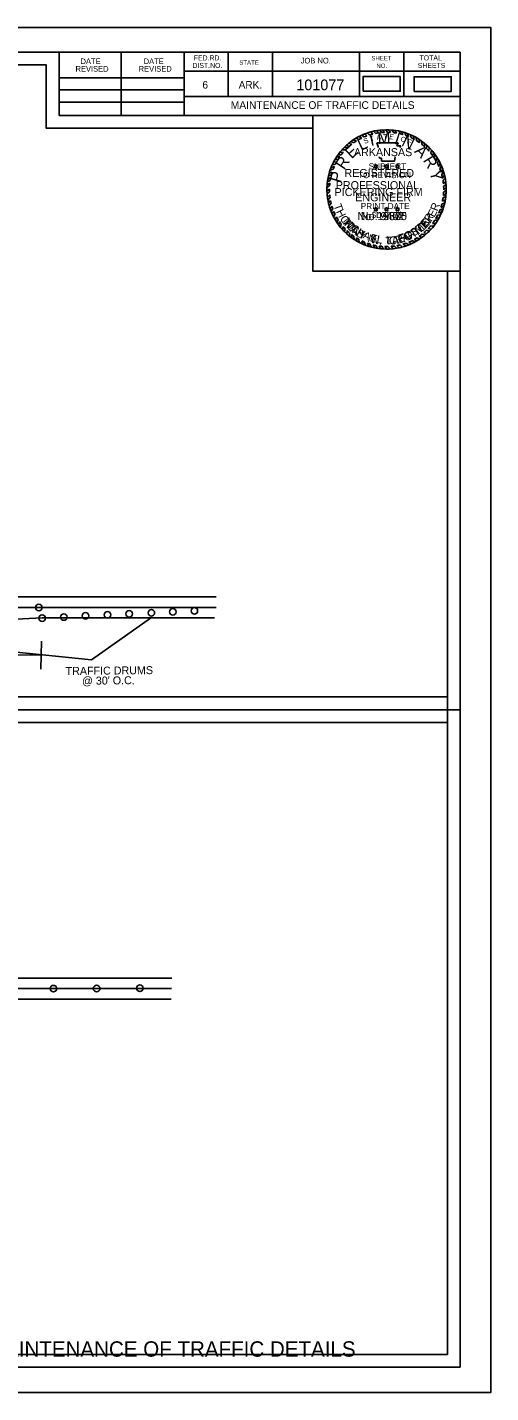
# Model space of a CAD drawing. Extents: x 13528 to 25043, y 7635 to 10612.
# Drawn here: x 18896 to 19258, y 9545 to 10612 of the extents above; entities that cross this region are included whole.
import ezdxf

# ---------------------------------------------------------------- set-up
doc = ezdxf.new("R2010")
doc.units = 0
for name, color, linetype in [('Default', 7, 'Continuous'), ('R_Border', 7, 'Continuous'), ('R_Border Notes', 7, 'Continuous'), ('R_Border Plan-Plan', 7, 'Continuous'), ('R_Draft', 7, 'Continuous'), ('R_Revision Date Text', 7, 'Continuous'), ('STAMP_PE_CRAFTON', 7, 'Continuous'), ('STAMP_PE_FOSTER', 7, 'Continuous'), ('STAMP_PE_SEAL-INFO', 7, 'Continuous'), ('STAMP_PE_TAEGTMEYER', 7, 'Continuous'), ('STAMP_PE_TXT', 7, 'Continuous')]:
    doc.layers.add(name, color=color, linetype=linetype)

# ---------------------------------------------------------------- blocks, each defined once
blk = doc.blocks.new('DOT')
at = {"layer": 'Default'}
blk.add_circle((-0.4, -0.3), 3.75, dxfattribs=at)

msp = doc.modelspace()

# ---------------------------------------------------------------- linework, layer by layer
at = {"layer": 'Default'}
for p, q in [((18002.2, 10166.6), (19044, 10166.6)), ((18002, 10158.4), (19043.8, 10158.4)), ((18737.5, 10142.1), (18908.1, 10150.2)), ((18908.2, 10150.2), (19042.6, 10150.2)), ((18907.6, 10131.9), (18907.1, 10110.1)), ((17907.8, 9868.7), (19009.2, 9868.7)), ((17907.6, 9860.5), (19009, 9860.5)), ((18865.7, 9852.3), (19008.8, 9852.3))]:
    msp.add_line(p, q, dxfattribs=at)
for points in [[(19158.6, 10561.6), (19187.7, 10561.6), (19187.7, 10573.1), (19158.6, 10573.1)], [(19198.5, 10561.4), (19227.5, 10561.4), (19227.5, 10572.9), (19198.5, 10572.9)]]:
    msp.add_lwpolyline(points, close=True, dxfattribs=at)
at = {"layer": 'R_Border'}
for p, q in [((18992.7, 10149.9), (18946.7, 10117.4)), ((18747, 10137.5), (18946.7, 10117.4)), ((18737.1, 10122.2), (18907.3, 10121))]:
    msp.add_line(p, q, dxfattribs=at)
at = {"layer": 'R_Border Plan-Plan'}
msp.add_line((17653.6, 10078.4), (19234.5, 10078.4), dxfattribs=at)
at = {"layer": 'R_Draft'}
for p, q in [((17653.6, 10592.1), (19234.5, 10592.1)), ((18921.3, 10542.7), (18921.3, 10592.1)), ((18969.7, 10542.7), (18969.7, 10592.1)), ((19019, 10592.1), (19019, 10542.7)), ((19053.2, 10592.1), (19053.2, 10557.4)), ((19087.9, 10592.1), (19087.9, 10557.4)), ((19155.8, 10592.1), (19155.8, 10557.4)), ((19190.5, 10592.1), (19190.5, 10557.4)), ((19234.5, 9564.8), (19234.5, 10592.1)), ((18921.3, 10572), (19019, 10572)), ((19234.5, 10577.4), (19019, 10577.4)), ((19234.5, 10577.5), (19234.5, 10577.5)), ((18921.3, 10562.7), (19019, 10562.7)), ((18921.3, 10553), (19019, 10553)), ((19234.5, 10557.4), (19019, 10557.4)), ((19033.8, 10557.4), (19234.5, 10557.4)), ((19234.5, 10542.7), (18921.3, 10542.7)), ((19234.5, 9564.8), (17653.6, 9564.8))]:
    msp.add_line(p, q, dxfattribs=at)
at = {"layer": 'R_Revision Date Text'}
for points in [[(17591.6, 10611.5), (19258.3, 10611.5), (19258.3, 9544.9), (17591.6, 9544.9)], [(19224.5, 10088.4), (17663.6, 10088.4), (17663.6, 10582.1), (18911.3, 10582.1), (18911.3, 10532.7), (18999, 10532.7), (19119.5, 10532.7), (19119.5, 10421), (19224.5, 10421)], [(17663.6, 10582.1), (18911.3, 10582.1), (18911.3, 10532.7), (18999, 10532.7), (19119.5, 10532.7), (19119.5, 10421), (19224.5, 10421), (19224.5, 9574.8), (17663.6, 9574.8)], [(19119.5, 10542.7), (19234.5, 10542.7), (19234.5, 10421), (19119.5, 10421)], [(17663.6, 10068.4), (19224.5, 10068.4), (19224.5, 9574.8), (17663.6, 9574.8)]]:
    msp.add_lwpolyline(points, close=True, dxfattribs=at)
at = {"layer": 'STAMP_PE_SEAL-INFO'}
for p, q in [((19160, 10528.3), (19161.5, 10526.7)), ((19161.8, 10529), (19163.7, 10527.4)), ((19164.7, 10529.9), (19166.2, 10528.1)), ((19166.7, 10530.3), (19168.5, 10528.6)), ((19169.1, 10530.8), (19170.6, 10529)), ((19171.7, 10531.2), (19173.1, 10529.3)), ((19175.3, 10529.4), (19173.8, 10531.4)), ((19177.8, 10529.4), (19176.4, 10531.5)), ((19180.1, 10529.3), (19178.8, 10531.5)), ((19182.7, 10529.1), (19181.2, 10531.3)), ((19184.8, 10528.8), (19183.5, 10531)), ((19187.6, 10528.2), (19186.7, 10530.5)), ((19189.6, 10527.6), (19188.8, 10530)), ((19191.9, 10526.9), (19191.2, 10529.3)), ((19194, 10526.1), (19193.2, 10528.6)), ((19143.8, 10517.6), (19146.5, 10517.4)), ((19145.5, 10519.2), (19147.8, 10518.5)), ((19147.2, 10520.7), (19149.8, 10520.2)), ((19149.1, 10522.4), (19151.4, 10521.3)), ((19151.2, 10523.7), (19153.4, 10522.7)), ((19153.1, 10524.9), (19155.3, 10523.8)), ((19155.4, 10526.2), (19157.7, 10525)), ((19157.5, 10527.2), (19159.5, 10525.9)), ((19169.4, 10521.3), (19186.1, 10521.3)), ((19170, 10519.8), (19169.4, 10521.3)), ((19170.5, 10518.3), (19170, 10519.8)), ((19170.5, 10517.7), (19170.5, 10518.3)), ((19186.1, 10521.3), (19184.9, 10518.9)), ((19184.9, 10518.9), (19188.1, 10518.9)), ((19188.1, 10518.9), (19187.4, 10517.7)), ((19196.3, 10525.1), (19195.7, 10527.6)), ((19198.5, 10523.9), (19198.1, 10526.5)), ((19200.4, 10522.8), (19200.2, 10525.3)), ((19202.6, 10521.4), (19202.4, 10523.9)), ((19204.4, 10520), (19204.6, 10522.5)), ((19206.6, 10518.2), (19206.7, 10520.8)), ((19208.2, 10516.7), (19208.5, 10519.2)), ((19136.7, 10508.3), (19139.1, 10508.4)), ((19137.9, 10510.3), (19140.5, 10510.4)), ((19139.1, 10512), (19141.6, 10512)), ((19140.5, 10513.8), (19143.2, 10513.9)), ((19142.2, 10515.9), (19144.8, 10515.7)), ((19171.5, 10509.2), (19171.3, 10510.3)), ((19173, 10509.2), (19171.5, 10509.2)), ((19173, 10507), (19173, 10509.2)), ((19183.2, 10507), (19173, 10507)), ((19183.3, 10508.7), (19183.2, 10507)), ((19183.7, 10510.3), (19183.3, 10508.7)), ((19210, 10514.8), (19210.3, 10517.5)), ((19211.4, 10513.3), (19212, 10515.6)), ((19213, 10511.2), (19213.7, 10513.7)), ((19214.1, 10509.6), (19215, 10511.9)), ((19215.6, 10507.1), (19216.5, 10509.6)), ((19216.6, 10505.3), (19217.8, 10507.5)), ((19131.6, 10495.5), (19133.9, 10496.4)), ((19132.1, 10497.5), (19134.5, 10498.3)), ((19132.9, 10500), (19135.3, 10500.7)), ((19133.6, 10502), (19136.2, 10502.8)), ((19134.6, 10504.2), (19137.1, 10504.7)), ((19135.5, 10506.1), (19138, 10506.5)), ((19217.8, 10502.9), (19218.9, 10505.3)), ((19218.5, 10501.2), (19219.8, 10503.3)), ((19219.5, 10498.4), (19220.8, 10500.8)), ((19220, 10496.6), (19221.5, 10498.9)), ((19132.5, 10487.6), (19130.4, 10486.3)), ((19132.7, 10489.8), (19130.5, 10488.3)), ((19133, 10491.9), (19130.8, 10490.8)), ((19133.4, 10494.2), (19131.1, 10493)), ((19220.7, 10493.8), (19222.2, 10496)), ((19221, 10491.9), (19222.8, 10493.7)), ((19221.3, 10489.4), (19223.2, 10491)), ((19221.5, 10487.3), (19223.4, 10488.7)), ((19221.6, 10484.7), (19223.6, 10486.3)), ((19132.4, 10485.2), (19130.4, 10483.5)), ((19132.5, 10483.1), (19130.5, 10481.5)), ((19132.6, 10480.6), (19130.8, 10478.9)), ((19132.9, 10478.5), (19131.1, 10476.6)), ((19133.3, 10476.2), (19131.6, 10474.4)), ((19220.6, 10475.7), (19222.9, 10476.7)), ((19221, 10478.2), (19223.3, 10479.3)), ((19221.3, 10480.1), (19223.5, 10481.4)), ((19221.5, 10482.7), (19223.6, 10484)), ((19133.7, 10474.1), (19132.2, 10472)), ((19134.4, 10471.9), (19132.9, 10469.8)), ((19135.1, 10469.8), (19133.7, 10467.7)), ((19135.9, 10467.6), (19134.6, 10465.5)), ((19136.8, 10465.7), (19135.6, 10463.4)), ((19216.8, 10464.8), (19219.2, 10465.1)), ((19217.6, 10466.5), (19220, 10467)), ((19218.6, 10469), (19221.1, 10469.7)), ((19219.3, 10470.9), (19221.8, 10472)), ((19220.1, 10473.4), (19222.4, 10474.4)), ((19137.9, 10463.4), (19137, 10461)), ((19139.1, 10461.4), (19138.2, 10459.1)), ((19140.1, 10459.8), (19139.6, 10457.1)), ((19141.5, 10457.9), (19141, 10455.2)), ((19143, 10456), (19142.6, 10453.4)), ((19144.6, 10454.3), (19144.2, 10451.7)), ((19209.4, 10454.3), (19211.8, 10453.9)), ((19211.3, 10456.5), (19213.6, 10456.1)), ((19212.9, 10458.4), (19215.4, 10458.4)), ((19214.6, 10460.9), (19216.9, 10460.9)), ((19215.4, 10462.3), (19217.9, 10462.6)), ((19146.2, 10452.7), (19146, 10450)), ((19147.9, 10451.1), (19147.9, 10448.5)), ((19149.7, 10449.7), (19149.8, 10447)), ((19151.4, 10448.4), (19151.6, 10445.8)), ((19153.5, 10447), (19153.8, 10444.4)), ((19155.3, 10446), (19155.7, 10443.4)), ((19157.7, 10444.7), (19158.5, 10442.1)), ((19159.5, 10443.9), (19160.4, 10441.3)), ((19162, 10442.9), (19163, 10440.4)), ((19192.2, 10443), (19194.4, 10441.7)), ((19194.3, 10443.8), (19196.4, 10442.5)), ((19196.6, 10444.9), (19199, 10443.8)), ((19198.6, 10445.9), (19200.7, 10444.8)), ((19200.7, 10447.2), (19203, 10446.2)), ((19202.4, 10448.3), (19204.6, 10447.4)), ((19204.7, 10450), (19207.1, 10449.3)), ((19206.1, 10451.1), (19208.5, 10450.5)), ((19208.1, 10453), (19210.3, 10452.3)), ((19164, 10442.2), (19165.2, 10439.8)), ((19166.6, 10441.5), (19167.7, 10439.2)), ((19168.6, 10441.1), (19169.8, 10438.8)), ((19171.1, 10440.7), (19172.3, 10438.5)), ((19173.3, 10440.5), (19174.6, 10438.3)), ((19175.7, 10440.3), (19177.2, 10438.3)), ((19178, 10440.3), (19179.7, 10438.4)), ((19180.6, 10440.5), (19182.2, 10438.6)), ((19182.8, 10440.7), (19184.6, 10438.9)), ((19185, 10441), (19186.9, 10439.3)), ((19187.5, 10441.6), (19189.3, 10439.9)), ((19189.8, 10442.2), (19191.8, 10440.7))]:
    msp.add_line(p, q, dxfattribs=at)
msp.add_circle((19177, 10484.9), 46.6, dxfattribs=at)
for radius, start, end in [(46.6, 111.3124, 114.7026), (46.6, 105.2339, 109.0352), (46.6, 99.7525, 102.7765), (44.6, 98.258, 101.0329), (46.6, 93.9381, 96.5517), (44.6, 92.1102, 95.0367), (46.6, 87.7298, 90.6707), (44.6, 85.9628, 88.9097), (46.6, 81.9732, 84.8236), (44.6, 79.9264, 82.696), (46.6, 75.3125, 77.9426), (46.6, 69.6061, 72.3058), (46.6, 135.4021, 138.3031), (46.6, 129.7326, 132.5376), (44.6, 127.5297, 130.9683), (46.6, 123.6199, 126.5906), (44.6, 121.9746, 125.11), (46.6, 117.6544, 120.8099), (44.6, 115.6869, 119.1583), (44.6, 110.3086, 113.1659), (44.6, 104.0352, 107.3615), (44.6, 73.5575, 76.2314), (44.6, 67.6248, 70.504), (46.6, 63.1329, 66.2704), (44.6, 61.1558, 64.3784), (46.6, 56.9003, 60.0942), (44.6, 54.9238, 58.2702), (44.6, 48.3016, 52.0395), (46.6, 50.3492, 53.7159), (46.6, 44.3405, 47.3929), (46.6, 147.0072, 149.899), (46.6, 141.6056, 144.4486), (44.6, 145.0197, 148.2104), (44.6, 139.301, 142.5873), (44.6, 133.1331, 136.2562), (44.6, 42.2212, 45.5512), (44.6, 36.135, 39.5311), (46.6, 38.1247, 41.2316), (44.6, 29.9032, 33.6645), (46.6, 31.9614, 35.4294), (46.6, 25.9391, 29.0125), (46.6, 164.3068, 166.894), (46.6, 158.4077, 161.0701), (44.6, 162.4331, 165.0013), (46.6, 152.864, 155.5189), (44.6, 156.3402, 159.2319), (44.6, 151.0315, 153.573), (44.6, 23.7732, 27.2211), (44.6, 17.6802, 21.4251), (46.6, 19.9538, 23.3141), (44.6, 11.5444, 15.2364), (46.6, 13.8421, 17.4447), (46.6, 175.7409, 178.2066), (46.6, 170.0003, 172.6878), (44.6, 173.73, 176.4734), (44.6, 167.9048, 170.9039), (44.6, 5.7599, 9.0606), (44.6, 359.7329, 3.0639), (46.6, 7.5852, 10.8621), (46.6, 1.7215, 4.7268), (46.6, 181.7251, 184.1626), (46.6, 187.4204, 190.1927), (44.6, 179.6454, 182.2633), (44.6, 185.4539, 188.234), (44.6, 191.2274, 193.9858), (44.6, 348.0778, 351.3435), (44.6, 353.8632, 357.1274), (46.6, 349.8305, 353.0885), (46.6, 355.7156, 358.9569), (46.6, 193.0369, 195.9973), (46.6, 198.8967, 201.6281), (44.6, 196.9675, 199.8353), (46.6, 204.5479, 207.4328), (44.6, 202.7761, 205.4791), (44.6, 329.5549, 333.2076), (44.6, 335.6038, 339.1858), (46.6, 331.4037, 334.9332), (44.6, 341.777, 345.0925), (46.6, 337.3837, 340.9933), (46.6, 343.8925, 347.035), (46.6, 210.8636, 213.6571), (44.6, 208.7883, 211.7934), (46.6, 216.6115, 219.491), (44.6, 214.1838, 217.2747), (44.6, 220.3909, 223.3056), (44.6, 316.6531, 320.3711), (46.6, 318.2846, 321.8043), (44.6, 323.5851, 327.4407), (46.6, 325.4405, 328.9872), (46.6, 222.48, 225.3801), (46.6, 228.3665, 231.348), (44.6, 226.2494, 229.2407), (44.6, 232.229, 234.9336), (46.6, 234.295, 236.9452), (44.6, 238.2223, 240.8353), (46.6, 240.1977, 242.8613), (44.6, 244.3204, 246.9486), (44.6, 250.3491, 253.1216), (44.6, 286.6423, 289.9783), (44.6, 292.8745, 296.1185), (46.6, 294.6481, 298.2166), (44.6, 299.0768, 302.1724), (46.6, 300.621, 303.8703), (44.6, 304.823, 308.5143), (46.6, 306.3721, 310.208), (44.6, 310.7744, 314.3161), (46.6, 312.4518, 315.6633), (46.6, 246.576, 249.1558), (46.6, 252.5967, 255.3252), (44.6, 256.505, 259.1192), (46.6, 258.4433, 261.1398), (44.6, 262.3783, 265.2012), (46.6, 264.1978, 267.1009), (44.6, 268.3215, 271.277), (46.6, 270.2548, 273.3361), (44.6, 274.6157, 277.4486), (46.6, 276.4239, 279.4357), (44.6, 280.3459, 283.5814), (46.6, 282.3199, 285.3702), (46.6, 288.5709, 291.9733)]:
    msp.add_arc((19177, 10484.9), radius, start, end, dxfattribs=at)
at = {"layer": 'STAMP_PE_TXT'}
for p, q in [((19167.9, 10502.7), (19166.9, 10503.5)), ((19166.9, 10503.5), (19168.1, 10503.5)), ((19167.5, 10501.6), (19167.9, 10502.7)), ((19168.5, 10502.3), (19167.5, 10501.6)), ((19168.1, 10503.5), (19168.5, 10504.6)), ((19168.5, 10504.6), (19168.9, 10503.5)), ((19169.5, 10501.6), (19168.5, 10502.3)), ((19168.9, 10503.5), (19170.1, 10503.5)), ((19170.1, 10503.5), (19169.1, 10502.7)), ((19169.1, 10502.7), (19169.5, 10501.6)), ((19176.4, 10502.7), (19175.4, 10503.5)), ((19175.4, 10503.5), (19176.6, 10503.5)), ((19176, 10501.6), (19176.4, 10502.7)), ((19177, 10502.3), (19176, 10501.6)), ((19176.6, 10503.5), (19177, 10504.6)), ((19177, 10504.6), (19177.4, 10503.5)), ((19178, 10501.6), (19177, 10502.3)), ((19177.4, 10503.5), (19178.6, 10503.5)), ((19178.6, 10503.5), (19177.6, 10502.7)), ((19177.6, 10502.7), (19178, 10501.6)), ((19184.9, 10502.7), (19183.9, 10503.5)), ((19183.9, 10503.5), (19185.1, 10503.5)), ((19184.5, 10501.6), (19184.9, 10502.7)), ((19185.5, 10502.3), (19184.5, 10501.6)), ((19185.1, 10503.5), (19185.5, 10504.6)), ((19185.5, 10504.6), (19185.9, 10503.5)), ((19186.5, 10501.6), (19185.5, 10502.3)), ((19185.9, 10503.5), (19187.1, 10503.5)), ((19187.1, 10503.5), (19186.1, 10502.7)), ((19186.1, 10502.7), (19186.5, 10501.6)), ((19167.9, 10469.2), (19166.9, 10469.9)), ((19166.9, 10469.9), (19168.1, 10469.9)), ((19167.5, 10468), (19167.9, 10469.2)), ((19168.5, 10468.8), (19167.5, 10468)), ((19168.1, 10469.9), (19168.5, 10471.1)), ((19168.5, 10471.1), (19168.9, 10469.9)), ((19169.5, 10468), (19168.5, 10468.8)), ((19168.9, 10469.9), (19170.1, 10469.9)), ((19170.1, 10469.9), (19169.1, 10469.2)), ((19169.1, 10469.2), (19169.5, 10468)), ((19176.4, 10469.2), (19175.4, 10469.9)), ((19175.4, 10469.9), (19176.6, 10469.9)), ((19176, 10468), (19176.4, 10469.2)), ((19177, 10468.8), (19176, 10468)), ((19176.6, 10469.9), (19177, 10471.1)), ((19177, 10471.1), (19177.4, 10469.9)), ((19178, 10468), (19177, 10468.8)), ((19177.4, 10469.9), (19178.6, 10469.9)), ((19178.6, 10469.9), (19177.6, 10469.2)), ((19177.6, 10469.2), (19178, 10468)), ((19184.9, 10469.2), (19183.9, 10469.9)), ((19183.9, 10469.9), (19185.1, 10469.9)), ((19184.5, 10468), (19184.9, 10469.2)), ((19185.5, 10468.8), (19184.5, 10468)), ((19185.1, 10469.9), (19185.5, 10471.1)), ((19185.5, 10471.1), (19185.9, 10469.9)), ((19186.5, 10468), (19185.5, 10468.8)), ((19185.9, 10469.9), (19187.1, 10469.9)), ((19187.1, 10469.9), (19186.1, 10469.2)), ((19186.1, 10469.2), (19186.5, 10468))]:
    msp.add_line(p, q, dxfattribs=at)

# ---------------------------------------------------------------- block references
at = {"layer": 'R_Border'}
for p, xscale, yscale, rotation in [((18905.8, 10158.4), 0.6809210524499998, 0.6809210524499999, -4.676990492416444), ((18959.4, 10152.7), 0.6809210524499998, 0.6809210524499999, -4.676990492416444), ((18976.3, 10153.5), 0.6809210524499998, 0.6809210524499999, -4.676990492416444), ((18993.6, 10154.3), 0.6809210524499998, 0.6809210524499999, -4.676990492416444), ((19010.3, 10155.1), 0.6809210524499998, 0.6809210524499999, -4.676990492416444), ((19027.2, 10155.9), 0.6809210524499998, 0.6809210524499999, -4.676990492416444), ((18908.3, 10150.2), 0.6809210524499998, 0.6809210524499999, -4.676990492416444), ((18925.2, 10151), 0.6809210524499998, 0.6809210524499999, -4.676990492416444), ((18942.2, 10151.9), 0.6809210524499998, 0.6809210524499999, -4.676990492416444), ((18917.1, 9860.7), 0.6809210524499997, 0.6809210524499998, -4.676990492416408), ((18950.9, 9860.8), 0.6809210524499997, 0.6809210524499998, -4.676990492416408), ((18984.7, 9861), 0.6809210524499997, 0.6809210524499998, -4.676990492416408)]:
    msp.add_blockref('DOT', p, dxfattribs=dict(at, xscale=xscale, yscale=yscale, rotation=rotation))

# ---------------------------------------------------------------- texts
for s, p in [('TRAFFIC DRUMS ', (18926.4, 10105.5)), ("@ 30' O.C.", (18939.2, 10097.9))]:
    msp.add_text(s, height=6.25, rotation=0.6305, dxfattribs=at).set_placement(p)
at = {"layer": 'R_Border Notes'}
for s, height, p in [('101077', 8.4, (19106.5, 10562.4)), ('MAINTENANCE OF TRAFFIC DETAILS', 6, (19055.3, 10547.8))]:
    msp.add_text(s, height=height, dxfattribs=at).set_placement(p)
at = {"layer": 'R_Border Plan-Plan'}
msp.add_text('MAINTENANCE OF TRAFFIC DETAILS', height=12, dxfattribs=at).set_placement((18865.7, 9573))
at = {"layer": 'R_Draft'}
for s, height, p in [('DATE', 4.4, (18938, 10582.8)), ('DATE', 4.4, (18987.3, 10582.8)), ('DIST.NO.', 3.91, (19025.4, 10579.8)), ('FED.RD.', 3.91, (19026.4, 10585.7)), ('STATE', 3.42, (19062, 10582.3)), ('JOB NO.', 4.4, (19109.9, 10583.3)), ('SHEET', 3.42, (19165.1, 10585.7)), ('NO.', 3.42, (19169, 10579.8)), ('SHEETS', 3.91, (19201.3, 10579.8)), ('TOTAL', 3.91, (19202.7, 10585.7)), ('REVISED', 4.4, (18934.1, 10576.9)), ('REVISED', 4.4, (18983.4, 10576.9)), ('6', 5.86, (19033.2, 10563.7)), ('ARK.', 5.86, (19061.5, 10563.7))]:
    msp.add_text(s, height=height, dxfattribs=at).set_placement(p)
at = {"layer": 'STAMP_PE_CRAFTON'}
msp.add_text('No. 12370', height=6.25, dxfattribs=at).set_placement((19154.3, 10460.9))
for s, rotation, p in [('T', 310.7442, (19141.8, 10459.4)), ('O', 317.6422, (19145.2, 10455.3)), ('N', 324.4537, (19149.4, 10451.4)), ('T', 34.1136, (19199.9, 10448.1)), ('O', 41.8391, (19204.2, 10451.1)), ('N', 49.2411, (19208.4, 10455)), ('Y', 331.1686, (19154.5, 10447.8)), ('N', 347.4752, (19164.8, 10443.2)), ('C', 6.0117, (19179.3, 10441.6)), ('R', 14.8189, (19184.8, 10442.2)), ('A', 20.5125, (19190.4, 10443.7)), ('F', 28.7821, (19195.3, 10445.5)), ('.', 356.8926, (19171, 10441.8))]:
    msp.add_text(s, height=6.25, rotation=rotation, dxfattribs=at).set_placement(p)
at = {"layer": 'STAMP_PE_FOSTER'}
msp.add_text('No. 9402', height=6.25, dxfattribs=at).set_placement((19156.9, 10460.9))
for s, rotation, p in [('R', 54.5031, (19210.6, 10458.9)), ('M', 308.339, (19142.6, 10460)), ('I', 314.1842, (19146.6, 10455.3)), ('C', 319.8733, (19148.3, 10453.5)), ('H', 327.7235, (19153, 10449.9)), ('S', 31.7234, (19197.9, 10447.9)), ('T', 39.4194, (19202.7, 10451.1)), ('E', 46.9613, (19207, 10454.8)), ('A', 335.7276, (19157.9, 10447)), ('E', 343.5779, (19163.6, 10444.6)), ('L', 350.8115, (19168.9, 10443.2)), ('L', 1.2666, (19176.6, 10442.4)), ('.', 6.8035, (19181.8, 10442.7)), ('F', 15.8691, (19187.2, 10443.7)), ('O', 23.719, (19192.4, 10445.3))]:
    msp.add_text(s, height=6, rotation=rotation, dxfattribs=at).set_placement(p)
at = {"layer": 'STAMP_PE_SEAL-INFO'}
for s, rotation, p in [('M', 3.1074, (19170.2, 10520.4)), ('I', 342.3164, (19182.5, 10520.7)), ('E', 42.3578, (19149.6, 10508.4)), ('L', 25.513, (19157, 10515)), ('I', 12.5248, (19164.7, 10518.8)), ('N', 333.9382, (19188, 10519.3)), ('A', 315.6579, (19198.2, 10514.2)), ('R', 56.2292, (19143.8, 10499.7)), ('R', 301.3831, (19205.1, 10507.6)), ('P', 73.913, (19141.1, 10489.6)), ('Y', 283.2593, (19210.5, 10498.7))]:
    msp.add_text(s, height=9, rotation=rotation, dxfattribs=at).set_placement(p)
for s, height, p in [('TO REVISION', 4.8, (19154.7, 10493.7)), ('SUBJECT', 4.8, (19163, 10500.6)), ('PICKERING FIRM', 6.25, (19136.4, 10479.7)), ('PRINT DATE', 4.8, (19156.8, 10469.5)), ('$DATE$', 4.8, (19165.2, 10462.5))]:
    msp.add_text(s, height=height, dxfattribs=at).set_placement(p)
at = {"layer": 'STAMP_PE_TAEGTMEYER'}
for s, rotation, p in [('T', 289.646, (19135.5, 10472.4)), ('H', 296.7339, (19137.3, 10467.5)), ('O', 303.7708, (19140.2, 10462)), ('Y', 53.9986, (19210.9, 10457.8)), ('E', 63.0984, (19214.2, 10462.6)), ('R', 69.57, (19216.7, 10467.5)), ('M', 314.2033, (19143.5, 10457.2)), ('A', 321.0594, (19148.3, 10452.4)), ('S', 327.8239, (19152.4, 10449.2)), ('T', 31.466, (19197.5, 10446.7)), ('M', 39.3, (19202, 10449.4)), ('E', 46.8094, (19207.2, 10453.8)), ('N', 344.2727, (19161.9, 10444.1)), ('.', 350.6464, (19168, 10442.5)), ('T', 3.0061, (19176.3, 10441.5)), ('A', 8.9826, (19181.5, 10441.8)), ('E', 17.6836, (19186.7, 10442.5)), ('G', 23.3052, (19192, 10444.2))]:
    msp.add_text(s, height=6.25, rotation=rotation, dxfattribs=at).set_placement(p)
msp.add_text('No. 19605', height=6.25, dxfattribs=at).set_placement((19154.3, 10460.9))
at = {"layer": 'STAMP_PE_TXT'}
for s, rotation, p in [('S', 23.5541, (19160, 10520.4)), ('T', 16.311, (19164.6, 10522.3)), ('A', 9.0679, (19169.4, 10523.5)), ('T', 1.8248, (19174.3, 10524.2)), ('E', 355.2002, (19178.9, 10524.2)), ('O', 342.2506, (19187.5, 10522.8)), ('F', 335.0075, (19192.4, 10521.1))]:
    msp.add_text(s, height=3.91, rotation=rotation, dxfattribs=at).set_placement(p)
for s, p in [('ARKANSAS', (19151.5, 10510.9)), ('REGISTERED', (19144.1, 10494.6)), ('PROFESSIONAL', (19137.3, 10485.1)), ('ENGINEER', (19152.5, 10475.6))]:
    msp.add_text(s, height=6.25, dxfattribs=at).set_placement(p)

doc.saveas('drawing.dxf')
